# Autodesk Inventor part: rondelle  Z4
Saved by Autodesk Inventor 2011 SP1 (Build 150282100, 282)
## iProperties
Created: 2010-12
Part Number: rondelle  Z4
Document SubType Name: Modeling
Designer: eric
Density: 1 g/cm^3
Author: eric
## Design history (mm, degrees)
feature "Base1"
node "Solide1"
node "Corps solides"
node "Corps surfaciques"
